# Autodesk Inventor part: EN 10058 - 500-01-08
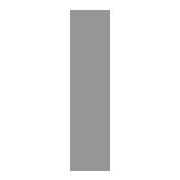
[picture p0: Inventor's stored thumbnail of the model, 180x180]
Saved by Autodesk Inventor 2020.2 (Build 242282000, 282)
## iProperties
Manager: www.cadconsulting.pl
Company: Fabian Stasiak CAD Consulting
Created: 2015-02
Part Number: EN 10058 - 500-01-08
Material: Stal
Description: Profile stalowe płaskie walcowane na gorąco do zastosowań ogólnych
Document SubType Name: Modeling
Standard: DIN EN 10058
Designer: F.Stasiak
Standard Revision: 2004
Standards Organization: DIN
Language: pl-PL
Size Designation: 60 x 10 - 870
Categories: <MemberInstance><Categories><Category DisplayName="Kształtowniki konstrukcyjne" InternalName="089c4875-fa83-4c05-b084-43b9cc11f5ed" Mnemonic="GRDR"><CategoryPar
Stock Number: 60 x 10
Density: 7.85 g/cm^3
Appearance: Płyta
IsCustomPart: 1
G_L: 870,000 mm
Author: F.Stasiak
Subject: Zbiór ćwiczeń. Autodesk Inventor 2020. Kurs podstawowy
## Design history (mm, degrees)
node "Płaszczyzna początkowa"
node "Płaszczyzna końcowa"
sketch "Szkic"
  geometry: L1 (5, -30)-(-5, -30); L2 (-5, -30)-(-5, 30); L3 (-5, 30)-(5, 30); L4 (5, 30)-(5, -30); L5 (-6, 0)-(8, 0); L6 (0, -30)-(0, 40); L7 (0, 54)-(0, -44) reference; L8 (-9.2, 0)-(13.2, 0) reference
  constraints: 12 end point, 2 collinear, 2 parallel, 1 horizontal, 1 perpendicular
  dimensions: "d0" = 60 distance between parallel lines of L3 L1 (= G_W); "d1" = 10 distance between parallel lines of L4 L2 (= G_H); "d4" = 5 distance between parallel lines of L6 L4 (= 0.5 x d1); "d5" = 30 distance between parallel lines of L5 L3 (= 0.5 x d0)
extrude "Bryła" new body sketch "Szkic" stored distance "d2" = 870 (= G_L); taper "d3" = 0 deg
node "Driven Length"
  sketch "Sketch3"
    geometry: L1 (0, 0)-(10, 0) reference
    constraints: 2 end point, 1 horizontal
  workplane "Work Plane3"
  sketch "Sketch4"
    geometry: L1 (-2, 0)-(12, 0) reference; L2 (-2, 870)-(12, 870) reference
    dimensions: "d9" = 870 distance between parallel lines of L1 L2 (derived)
body "Solid1"
other parameters: "G_W" = 60 [user parameter; used in 1 equation term], "G_H" = 10 [user parameter; used in 1 equation term], "G_L" = 870 (= d9) [user parameter; used in 1 equation term], "G_OFFSET_START" = 0 [user parameter; used in 1 equation term], "G_OFFSET_END" = 0 [user parameter; used in 1 equation term], "d6" = 0 (computed from G_OFFSET_START), "d8" = 90 deg, "MAS" = 0.471 [user parameter]
